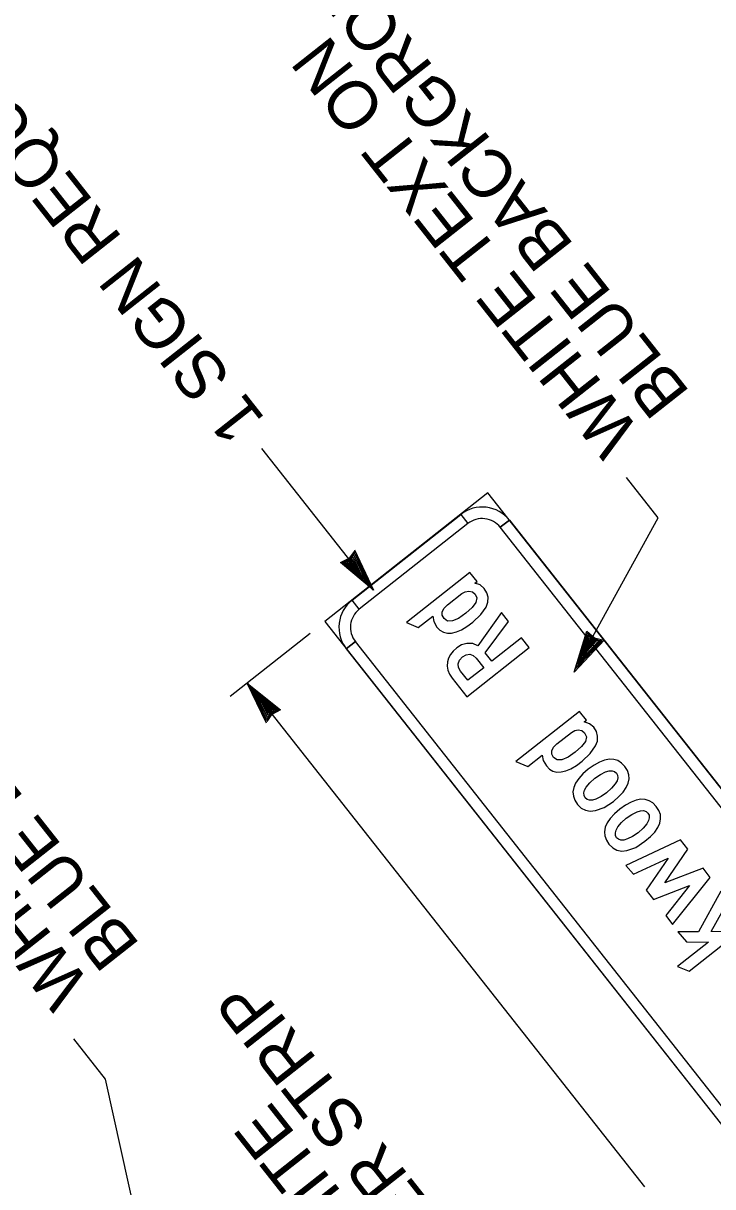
# Model space of a CAD drawing. Extents: x 671946 to 673995, y 1673066 to 1674936.
# Drawn here: x 672428.5 to 672488.3, y 1673831.7 to 1673932.5 of the extents above; entities that cross this region are included whole.
import ezdxf

# ---------------------------------------------------------------- set-up
doc = ezdxf.new("R2010")
doc.units = 0
doc.layers.add('C-ANNO-SYMB', color=7, linetype='Continuous')
doc.layers.add('Level 1', color=7, linetype='Continuous')

msp = doc.modelspace()

# ---------------------------------------------------------------- linework, layer by layer
at = {"layer": 'C-ANNO-SYMB'}
for p, q in [((672468.82, 1673891.85), (672454.69, 1673880.7)), ((672546.83, 1673792.9), (672468.82, 1673891.85)), ((672457.04, 1673882.56), (672466.47, 1673889.99)), ((672467.08, 1673889.2), (672457.66, 1673881.77)), ((672466.47, 1673889.99), (672467.08, 1673889.2)), ((672466.47, 1673889.99), (672467.08, 1673889.2)), ((672467.08, 1673889.2), (672467.08, 1673889.2)), ((672467.08, 1673889.2), (672467.08, 1673889.2)), ((672469.89, 1673888.87), (672470.68, 1673889.49)), ((672470.68, 1673889.49), (672469.89, 1673888.87)), ((672470.68, 1673889.49), (672544.97, 1673795.25)), ((672544.19, 1673794.63), (672469.89, 1673888.87)), ((672457.66, 1673881.77), (672457.04, 1673882.56)), ((672457.66, 1673881.77), (672457.04, 1673882.56)), ((672457.66, 1673881.77), (672457.04, 1673882.56)), ((672454.69, 1673880.7), (672532.69, 1673781.75)), ((672456.54, 1673878.35), (672457.33, 1673878.97)), ((672457.33, 1673878.97), (672456.54, 1673878.35)), ((672456.54, 1673878.35), (672530.83, 1673784.11)), ((672457.33, 1673878.97), (672457.33, 1673878.97)), ((672457.33, 1673878.97), (672457.33, 1673878.97)), ((672531.62, 1673784.73), (672457.33, 1673878.97))]:
    msp.add_line(p, q, dxfattribs=at)
for points in [[(672467.87, 1673884.18), (672467.26, 1673884.95), (672461.76, 1673880.61), (672462.78, 1673880.18), (672464.03, 1673881.16), (672464.12, 1673880.71), (672464.4, 1673880.23), (672464.66, 1673879.96), (672464.96, 1673879.79), (672465.3, 1673879.7), (672465.67, 1673879.71), (672466.08, 1673879.8), (672466.52, 1673879.99), (672466.99, 1673880.27), (672467.5, 1673880.64), (672468.2, 1673881.3), (672468.65, 1673881.95), (672468.81, 1673882.39), (672468.83, 1673882.81), (672468.73, 1673883.2), (672468.5, 1673883.58), (672468.13, 1673883.89), (672467.68, 1673884.04), (672467.87, 1673884.18)], [(672466.56, 1673883.13), (672466.85, 1673883.29), (672467.15, 1673883.35), (672467.47, 1673883.29), (672467.71, 1673883.09), (672467.85, 1673882.75), (672467.76, 1673882.35), (672467.45, 1673881.91), (672466.9, 1673881.42), (672466.27, 1673880.98), (672465.74, 1673880.76), (672465.32, 1673880.75), (672465.01, 1673880.96), (672464.86, 1673881.25), (672464.86, 1673881.55), (672465.01, 1673881.85), (672465.31, 1673882.15), (672466.56, 1673883.13)], [(672472.39, 1673878.44), (672471.72, 1673879.28), (672469.16, 1673877.26), (672468.59, 1673877.98), (672470.6, 1673880.71), (672469.99, 1673881.48), (672467.95, 1673878.6), (672467.5, 1673878.79), (672467, 1673878.81), (672466.54, 1673878.68), (672466.11, 1673878.42), (672465.8, 1673878.14), (672465.57, 1673877.84), (672465.4, 1673877.53), (672465.31, 1673877.2), (672465.29, 1673876.84), (672465.35, 1673876.49), (672465.5, 1673876.14), (672465.73, 1673875.8), (672467, 1673874.19), (672472.39, 1673878.44)], [(672468.45, 1673876.7), (672467.07, 1673875.62), (672466.45, 1673876.41), (672466.28, 1673876.72), (672466.24, 1673877.05), (672466.35, 1673877.37), (672466.6, 1673877.64), (672466.93, 1673877.83), (672467.24, 1673877.88), (672467.53, 1673877.77), (672467.8, 1673877.52), (672468.45, 1673876.7)], [(672477.36, 1673872.15), (672476.75, 1673872.91), (672471.25, 1673868.57), (672472.27, 1673868.14), (672473.52, 1673869.12), (672473.61, 1673868.67), (672473.89, 1673868.2), (672474.15, 1673867.92), (672474.45, 1673867.75), (672474.79, 1673867.66), (672475.16, 1673867.67), (672475.57, 1673867.76), (672476.01, 1673867.95), (672476.48, 1673868.23), (672476.99, 1673868.6), (672477.69, 1673869.26), (672478.14, 1673869.92), (672478.3, 1673870.35), (672478.32, 1673870.77), (672478.22, 1673871.17), (672477.99, 1673871.54), (672477.62, 1673871.85), (672477.17, 1673872), (672477.36, 1673872.15)], [(672476.05, 1673871.09), (672476.34, 1673871.25), (672476.64, 1673871.31), (672476.96, 1673871.25), (672477.2, 1673871.06), (672477.35, 1673870.71), (672477.26, 1673870.31), (672476.94, 1673869.87), (672476.39, 1673869.38), (672475.76, 1673868.94), (672475.23, 1673868.72), (672474.81, 1673868.71), (672474.5, 1673868.93), (672474.35, 1673869.21), (672474.35, 1673869.51), (672474.5, 1673869.81), (672474.8, 1673870.11), (672476.05, 1673871.09)], [(672477.51, 1673867.9), (672477.05, 1673867.5), (672476.69, 1673867.1), (672476.42, 1673866.71), (672476.25, 1673866.33), (672476.19, 1673865.95), (672476.22, 1673865.58), (672476.35, 1673865.22), (672476.58, 1673864.86), (672476.9, 1673864.54), (672477.27, 1673864.35), (672477.68, 1673864.27), (672478.14, 1673864.32), (672478.9, 1673864.6), (672479.7, 1673865.12), (672480.17, 1673865.53), (672480.54, 1673865.93), (672480.81, 1673866.31), (672480.98, 1673866.69), (672481.05, 1673867.07), (672481.03, 1673867.43), (672480.9, 1673867.79), (672480.68, 1673868.14), (672480.39, 1673868.44), (672480.07, 1673868.65), (672479.72, 1673868.76), (672479.34, 1673868.78), (672478.93, 1673868.7), (672478.49, 1673868.52), (672478.02, 1673868.26), (672477.51, 1673867.9)], [(672478.08, 1673867.12), (672478.56, 1673867.46), (672479.01, 1673867.69), (672479.32, 1673867.77), (672479.58, 1673867.78), (672479.79, 1673867.72), (672479.96, 1673867.57), (672480.06, 1673867.38), (672480.07, 1673867.16), (672480.01, 1673866.91), (672479.85, 1673866.64), (672479.53, 1673866.25), (672479.1, 1673865.87), (672478.63, 1673865.54), (672478.18, 1673865.32), (672477.88, 1673865.23), (672477.62, 1673865.22), (672477.41, 1673865.29), (672477.24, 1673865.44), (672477.15, 1673865.63), (672477.13, 1673865.85), (672477.2, 1673866.09), (672477.34, 1673866.36), (672477.66, 1673866.74), (672478.08, 1673867.12)], [(672480.24, 1673864.43), (672479.78, 1673864.03), (672479.42, 1673863.64), (672479.15, 1673863.25), (672478.98, 1673862.87), (672478.92, 1673862.49), (672478.95, 1673862.12), (672479.08, 1673861.75), (672479.31, 1673861.4), (672479.63, 1673861.08), (672480, 1673860.88), (672480.41, 1673860.81), (672480.87, 1673860.85), (672481.63, 1673861.13), (672482.43, 1673861.66), (672482.9, 1673862.07), (672483.27, 1673862.46), (672483.54, 1673862.85), (672483.71, 1673863.23), (672483.78, 1673863.6), (672483.76, 1673863.97), (672483.63, 1673864.33), (672483.41, 1673864.68), (672483.12, 1673864.98), (672482.8, 1673865.18), (672482.45, 1673865.29), (672482.07, 1673865.31), (672481.66, 1673865.23), (672481.22, 1673865.06), (672480.75, 1673864.8), (672480.24, 1673864.43)], [(672480.81, 1673863.66), (672481.29, 1673863.99), (672481.75, 1673864.22), (672482.05, 1673864.31), (672482.31, 1673864.32), (672482.52, 1673864.25), (672482.69, 1673864.11), (672482.79, 1673863.92), (672482.8, 1673863.69), (672482.74, 1673863.45), (672482.58, 1673863.17), (672482.26, 1673862.79), (672481.83, 1673862.4), (672481.36, 1673862.07), (672480.91, 1673861.86), (672480.61, 1673861.77), (672480.35, 1673861.76), (672480.14, 1673861.83), (672479.97, 1673861.97), (672479.88, 1673862.16), (672479.86, 1673862.38), (672479.93, 1673862.63), (672480.07, 1673862.9), (672480.39, 1673863.28), (672480.81, 1673863.66)]]:
    msp.add_lwpolyline(points, dxfattribs=at)
for points in [[(672484.8, 1673854.44), (672488.09, 1673858.52), (672487.46, 1673859.32), (672484.16, 1673858.07), (672486.15, 1673860.98), (672485.51, 1673861.8), (672480.77, 1673859.55), (672481.43, 1673858.8), (672484.45, 1673860.19), (672482.52, 1673857.42), (672483.16, 1673856.61), (672486.3, 1673857.82), (672484.24, 1673855.23)], [(672491.33, 1673854.41), (672490.74, 1673855.15), (672489.03, 1673853.8), (672488.17, 1673853.83), (672489.66, 1673856.53), (672489.01, 1673857.35), (672487.06, 1673853.82), (672485.28, 1673853.82), (672486.04, 1673852.95), (672487.92, 1673852.93), (672485.25, 1673850.82), (672486.25, 1673850.41)]]:
    msp.add_lwpolyline(points, close=True, dxfattribs=at)
for centre, radius, start, end in [((672468.32, 1673887.63), 3, 38.2506, 128.2508), ((672468.32, 1673887.63), 2, 38.2506, 128.2508), ((672458.9, 1673880.2), 3, 128.2505, 218.2508), ((672458.9, 1673880.2), 2, 128.2505, 218.2508)]:
    msp.add_arc(centre, radius, start, end, dxfattribs=at)
at = {"layer": 'Level 1'}
for p, q in [((672458.89, 1673883.43), (672449.23, 1673895.69)), ((672456.03, 1673885.82), (672456.8, 1673886.19)), ((672456.18, 1673885.79), (672456.75, 1673886.12)), ((672456.48, 1673885.79), (672457.19, 1673886.45)), ((672456.61, 1673885.92), (672457.19, 1673886.45)), ((672456.61, 1673885.83), (672457.13, 1673886.27)), ((672456.75, 1673886.12), (672457.24, 1673886.78)), ((672457.02, 1673886.2), (672456.75, 1673885.83)), ((672456.76, 1673885.77), (672457.09, 1673886.11)), ((672456.8, 1673886.19), (672457.11, 1673886.43)), ((672457.03, 1673885.84), (672457.02, 1673886.2)), ((672457.09, 1673886.11), (672457.58, 1673885.14)), ((672457.11, 1673886.43), (672457.31, 1673886.74)), ((672457.13, 1673886.27), (672457.84, 1673884.75)), ((672457.24, 1673886.78), (672457.17, 1673886.57)), ((672457.17, 1673886.57), (672457.27, 1673886.57)), ((672457.19, 1673886.45), (672458.17, 1673884.31)), ((672457.19, 1673886.45), (672458.3, 1673884.23)), ((672457.26, 1673886.93), (672458.89, 1673883.43)), ((672457.27, 1673886.57), (672458.63, 1673883.7)), ((672457.31, 1673886.74), (672458.54, 1673883.86)), ((672458.89, 1673883.43), (672456.03, 1673885.82)), ((672458.66, 1673883.66), (672456.18, 1673885.79)), ((672456.35, 1673885.79), (672456.61, 1673885.92)), ((672458.39, 1673884.01), (672456.35, 1673885.79)), ((672458.17, 1673884.31), (672456.48, 1673885.79)), ((672458.3, 1673884.23), (672456.61, 1673885.83)), ((672456.75, 1673885.83), (672457.49, 1673885.3)), ((672457.84, 1673884.75), (672456.76, 1673885.77)), ((672456.88, 1673885.73), (672457.04, 1673886.01)), ((672457.58, 1673885.14), (672456.88, 1673885.73)), ((672456.96, 1673885.76), (672457.03, 1673885.84)), ((672457.3, 1673885.48), (672456.96, 1673885.76)), ((672457.04, 1673886.01), (672457.3, 1673885.48)), ((672457.49, 1673885.3), (672457.59, 1673885.05)), ((672453.4, 1673879.67), (672446.49, 1673874.22)), ((672476.28, 1673876.31), (672477.4, 1673879.86)), ((672478.93, 1673879.11), (672476.28, 1673876.31)), ((672476.4, 1673876.61), (672477.43, 1673879.71)), ((672478.73, 1673879.03), (672476.54, 1673876.79)), ((672476.63, 1673876.99), (672477.49, 1673879.55)), ((672476.79, 1673877.16), (672477.63, 1673879.32)), ((672478.43, 1673879.03), (672476.79, 1673877.16)), ((672476.82, 1673877.3), (672477.54, 1673879.43)), ((672478.43, 1673879.03), (672476.82, 1673877.3)), ((672477.1, 1673877.78), (672477.63, 1673879.17)), ((672478.24, 1673879.02), (672477.1, 1673877.78)), ((672477.36, 1673878.17), (672477.64, 1673879.04)), ((672477.4, 1673879.86), (672478.04, 1673879.29)), ((672477.43, 1673879.71), (672477.95, 1673879.31)), ((672477.68, 1673879.2), (672477.48, 1673878.31)), ((672477.49, 1673879.55), (672477.71, 1673879.36)), ((672477.54, 1673879.43), (672478.43, 1673879.03)), ((672477.63, 1673879.32), (672478.24, 1673879.02)), ((672477.63, 1673879.17), (672478.07, 1673879)), ((672477.64, 1673879.04), (672477.95, 1673879)), ((672478.13, 1673879.08), (672477.68, 1673879.2)), ((672477.71, 1673879.36), (672478.43, 1673879.03)), ((672477.8, 1673878.94), (672478.13, 1673879.08)), ((672477.95, 1673879.31), (672478.75, 1673879.11)), ((672478.04, 1673879.29), (672478.37, 1673879.09)), ((672478.37, 1673879.09), (672478.73, 1673879.03)), ((672478.52, 1673879.09), (672478.57, 1673879)), ((672478.57, 1673879), (672476.43, 1673876.65)), ((672477.28, 1673878.13), (672477.07, 1673877.67)), ((672477.07, 1673877.67), (672477.4, 1673878.02)), ((672477.48, 1673878.31), (672477.28, 1673878.13)), ((672478.07, 1673879), (672477.36, 1673878.17)), ((672477.95, 1673879), (672477.57, 1673878.56)), ((672477.57, 1673878.56), (672477.7, 1673878.98)), ((672477.7, 1673878.98), (672477.8, 1673878.94)), ((672476.61, 1673876.75), (672477.2, 1673877.44)), ((672477.2, 1673877.44), (672476.63, 1673876.99)), ((672449.64, 1673871.9), (672447.94, 1673875.36)), ((672447.94, 1673875.36), (672450.85, 1673873.04)), ((672482.41, 1673831.71), (672447.97, 1673875.39)), ((672448.3, 1673874.94), (672448.17, 1673875.15)), ((672448.17, 1673875.15), (672450.7, 1673873.06)), ((672449.63, 1673872.26), (672448.21, 1673875.1)), ((672448.21, 1673875.1), (672448.24, 1673874.9)), ((672448.24, 1673874.9), (672448.66, 1673874.1)), ((672449.59, 1673872.09), (672448.3, 1673874.94)), ((672448.66, 1673874.1), (672448.45, 1673874.79)), ((672448.45, 1673874.79), (672450.53, 1673873.06)), ((672449.7, 1673872.38), (672448.55, 1673874.58)), ((672448.55, 1673874.58), (672450.26, 1673873.02)), ((672449.7, 1673872.38), (672448.67, 1673874.5)), ((672448.67, 1673874.5), (672450.4, 1673873.06)), ((672449.27, 1673873.78), (672448.93, 1673874.14)), ((672448.93, 1673874.14), (672449.13, 1673873.7)), ((672449.76, 1673872.56), (672449.01, 1673874.07)), ((672449.01, 1673874.07), (672450.12, 1673873.08)), ((672449.38, 1673873.52), (672449.27, 1673873.78)), ((672449.8, 1673872.72), (672449.28, 1673873.68)), ((672449.28, 1673873.68), (672449.99, 1673873.11)), ((672450.13, 1673873.02), (672449.38, 1673873.52)), ((672449.85, 1673872.83), (672449.58, 1673873.35)), ((672449.58, 1673873.35), (672449.92, 1673873.08)), ((672450.4, 1673873.06), (672449.7, 1673872.38)), ((672450.26, 1673873.02), (672449.76, 1673872.56)), ((672450.12, 1673873.08), (672449.8, 1673872.72)), ((672449.99, 1673873.11), (672449.85, 1673872.83)), ((672449.92, 1673873.08), (672449.85, 1673873)), ((672449.85, 1673873), (672449.86, 1673872.64)), ((672449.86, 1673872.64), (672450.13, 1673873.02)), ((672450.85, 1673873.04), (672450.09, 1673872.65)), ((672450.7, 1673873.06), (672450.13, 1673872.72)), ((672450.53, 1673873.06), (672450.27, 1673872.92)), ((672449.78, 1673872.41), (672449.59, 1673872.09)), ((672449.72, 1673872.27), (672449.63, 1673872.26)), ((672450.13, 1673872.72), (672449.66, 1673872.05)), ((672450.27, 1673872.92), (672449.7, 1673872.38)), ((672450.09, 1673872.65), (672449.78, 1673872.41))]:
    msp.add_line(p, q, dxfattribs=at)
for points in [[(672477.42, 1673878.52), (672483.58, 1673889.69), (672480.83, 1673893.18)], [(672440.39, 1673819.77), (672435.68, 1673841.05), (672432.93, 1673844.54)]]:
    msp.add_lwpolyline(points, dxfattribs=at)

# ---------------------------------------------------------------- texts
for s, p in [('BLUE BACKGROUND', (672486.41, 1673900.53)), ('1 SIGN REQUIRED', (672449.59, 1673898.22)), ('WHITE TEXT ON', (672482.11, 1673897.14)), ('BLUE BACKGROUND', (672438.74, 1673852.66)), ('WHITE TEXT ON', (672434.45, 1673849.28)), ('BORDER STRIP', (672474.38, 1673816.99)), ('0.75" WHITE ', (672470.08, 1673813.61))]:
    msp.add_text(s, height=4.2, rotation=128.2505, dxfattribs=at).set_placement(p)

doc.saveas('drawing.dxf')
